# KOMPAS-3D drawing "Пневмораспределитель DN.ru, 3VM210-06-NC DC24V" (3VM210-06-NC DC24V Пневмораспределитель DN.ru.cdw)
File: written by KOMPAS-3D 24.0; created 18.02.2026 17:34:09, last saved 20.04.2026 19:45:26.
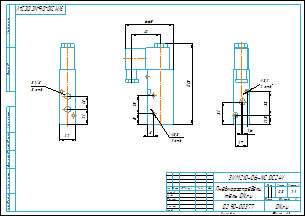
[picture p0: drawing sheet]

Document properties: Автор: R2D2; Форматы листов документа: A3; Полное имя файла: ..\AC24V\3VM210-06-NC AC24V Пневмораспредели тель DN.ru.cdw; Масса: 0.3; Наименование: Пневмораспределитель DN.ru; Количество листов документа: 1; Примечание: D290-00377

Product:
- Part/product: Пневмораспределитель DN.ru  | designation 3VM210-06-NC DC24V
    Масса: 0.3
    Раздел спецификации: Прочие изделия
    Форматы листов документа: A3
    Примечание: D290-00377

Views: Вид 1, Спереди, Проекционный вид 2, Проекционный вид 3
Referenced files in E:\Работа\Зайцев\Аксессуары для пневмоприводов\Пневмораспределители DN.ru\3VM210-06-NC Пневмораспределитель DN.RU\AC24V\: 3VM210-06-NC AC24V Пневмораспределитель DN.ru.m3d
Referenced files in E:\Работа\Зайцев\Аксессуары для пневмоприводов\Пневмораспределители DN.ru\3VM210-06-NC Пневмораспределитель DN.RU\DC24V\: 3VM210-06-NC DC24V Пневмораспределитель DN.ru.m3d
Referenced files in E:\Работа\Зайцев\Для компаса\: чертеж DN.ru А3.cdt
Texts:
  Линейный размер
  чертеж DN.ru А3.cdt
  Пневмораспредели
  тель DN.ru
  Пневмораспределитель DN.ru
  3VM210-06-NC DC24V Пневмораспределитель DN.ru
Dimensions and other numbers on the sheet: 0; 3; 2; 4; 3 отв.; 21; 18; 22; 3VM210-06-NC DC24V; 66,5; 40; 111,5; 3,3; 2 отв.; 15; 25; 8; 3,2; 33; 12,5; 17; 1,6; 31; 1:1; 1; 0,3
